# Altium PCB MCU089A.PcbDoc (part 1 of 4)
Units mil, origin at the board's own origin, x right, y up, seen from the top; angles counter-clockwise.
Board outline 2300 x 5500 mil, 4 copper layers (Top Signal, GND, PWR, Bottom Signal), stack 61.6 mil thick; 262 components, 208 nets, 964 pads, 377 vias.
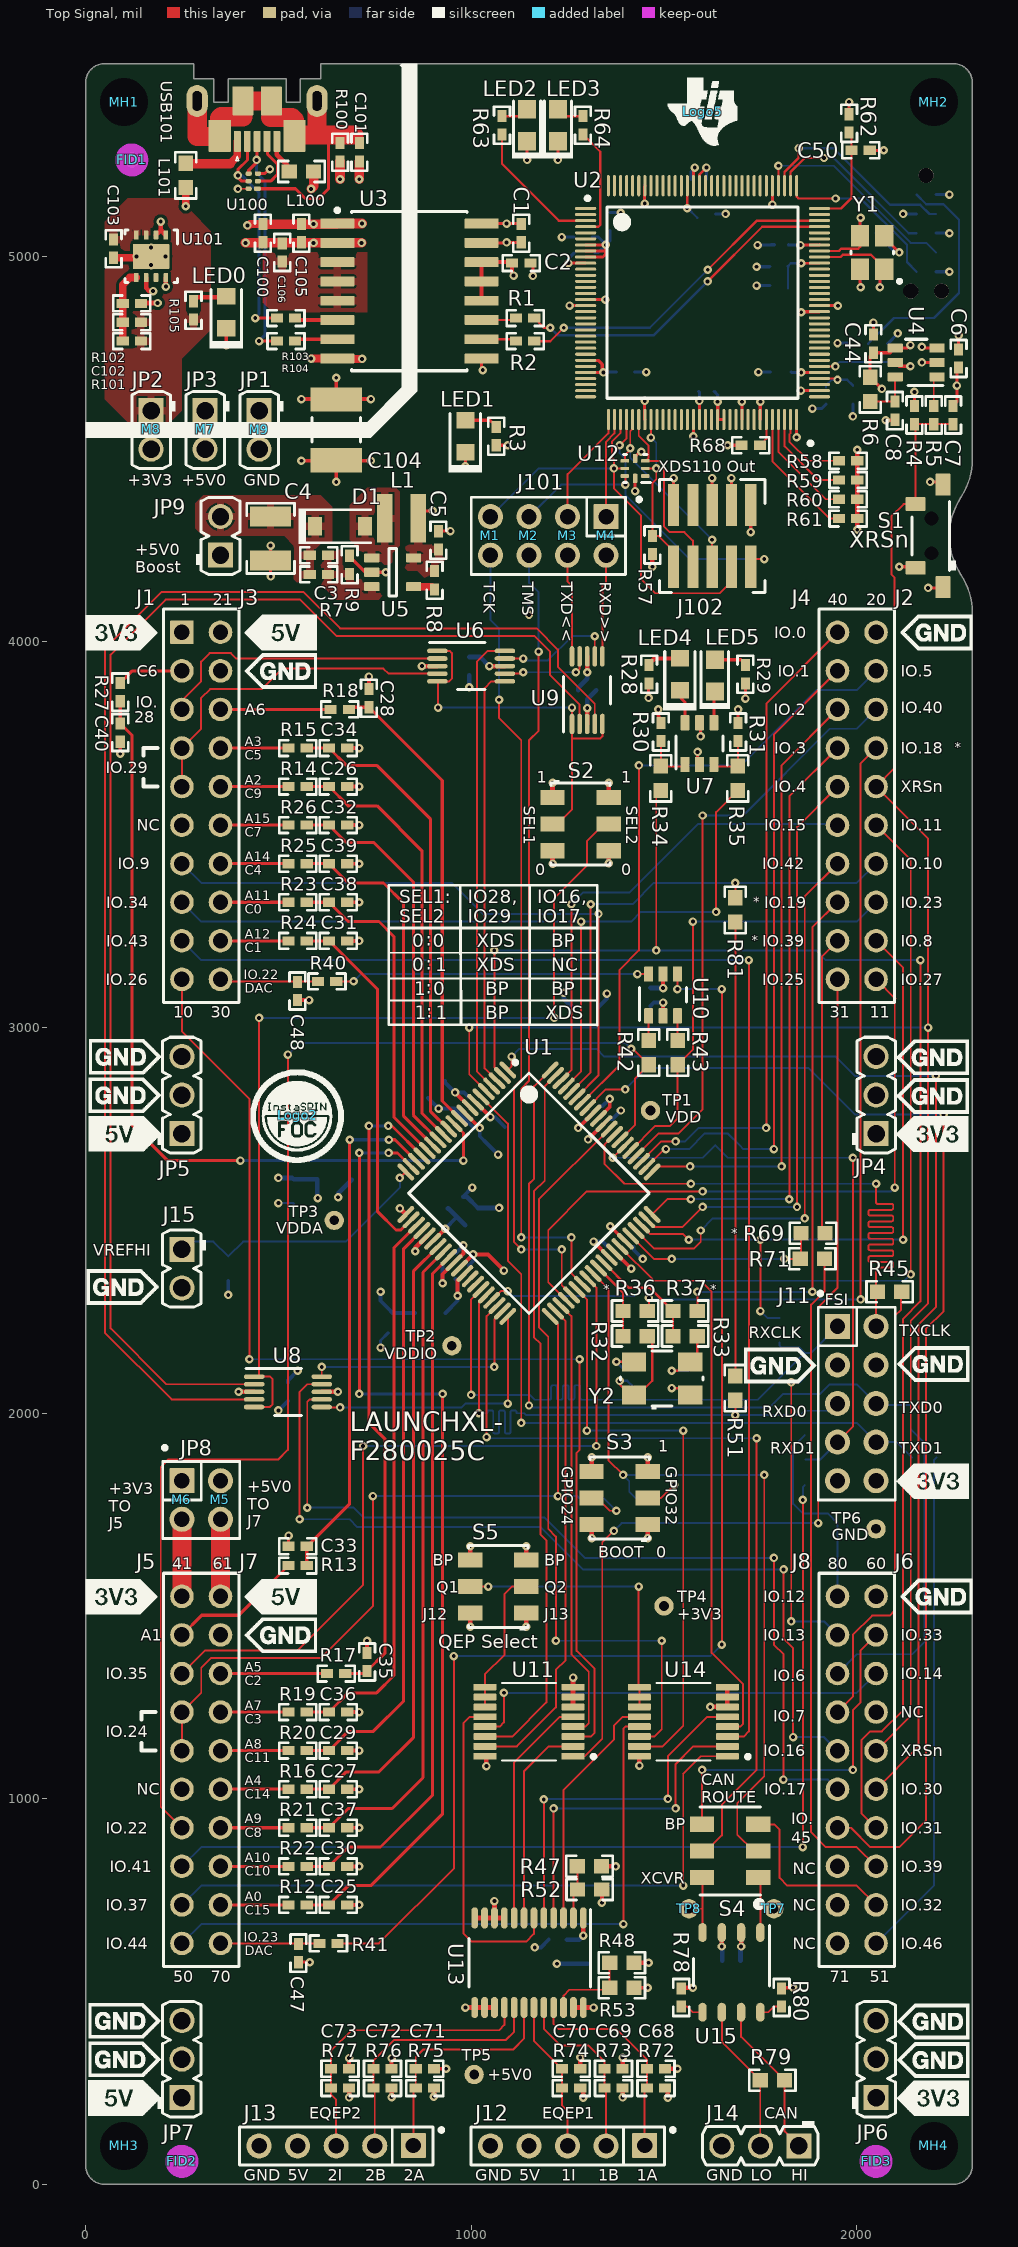
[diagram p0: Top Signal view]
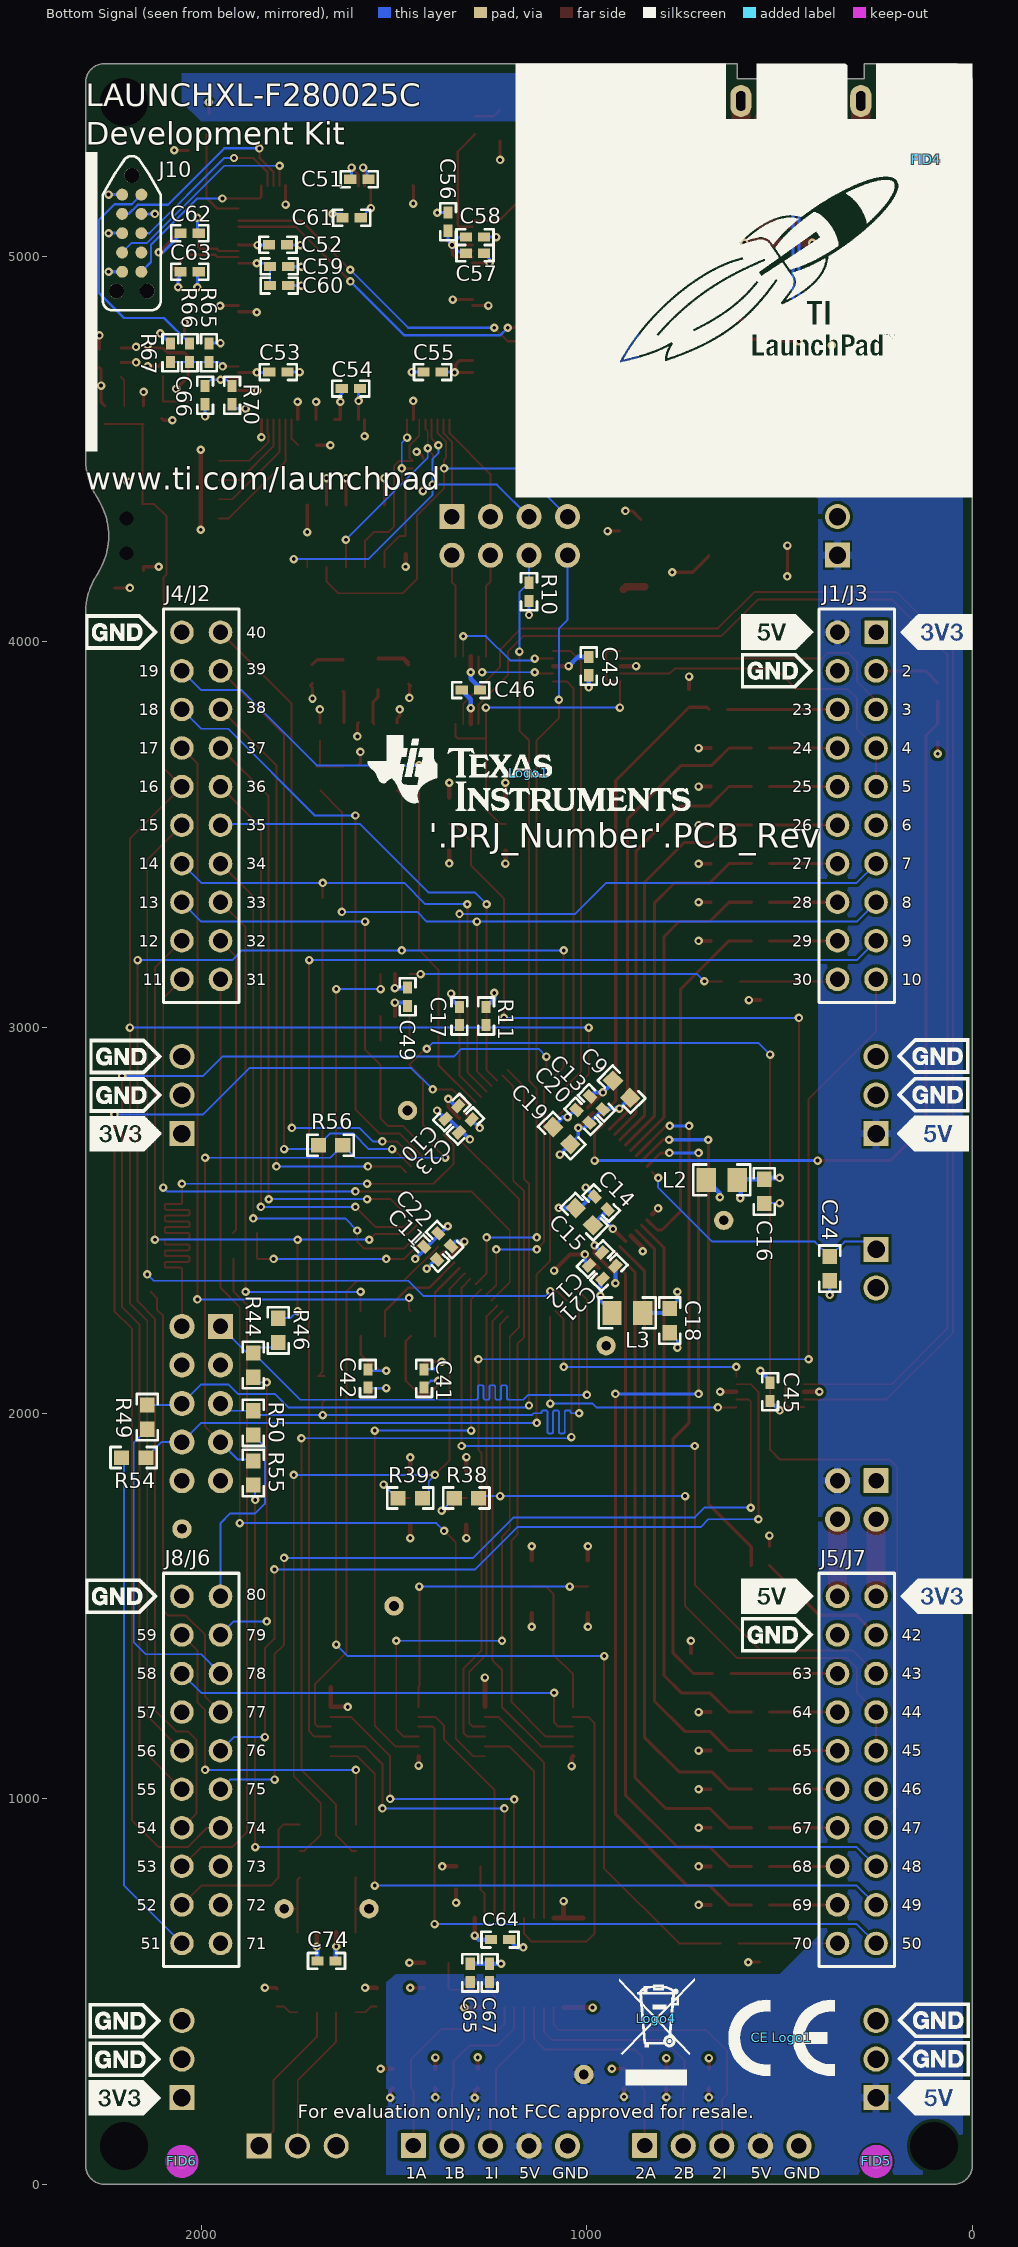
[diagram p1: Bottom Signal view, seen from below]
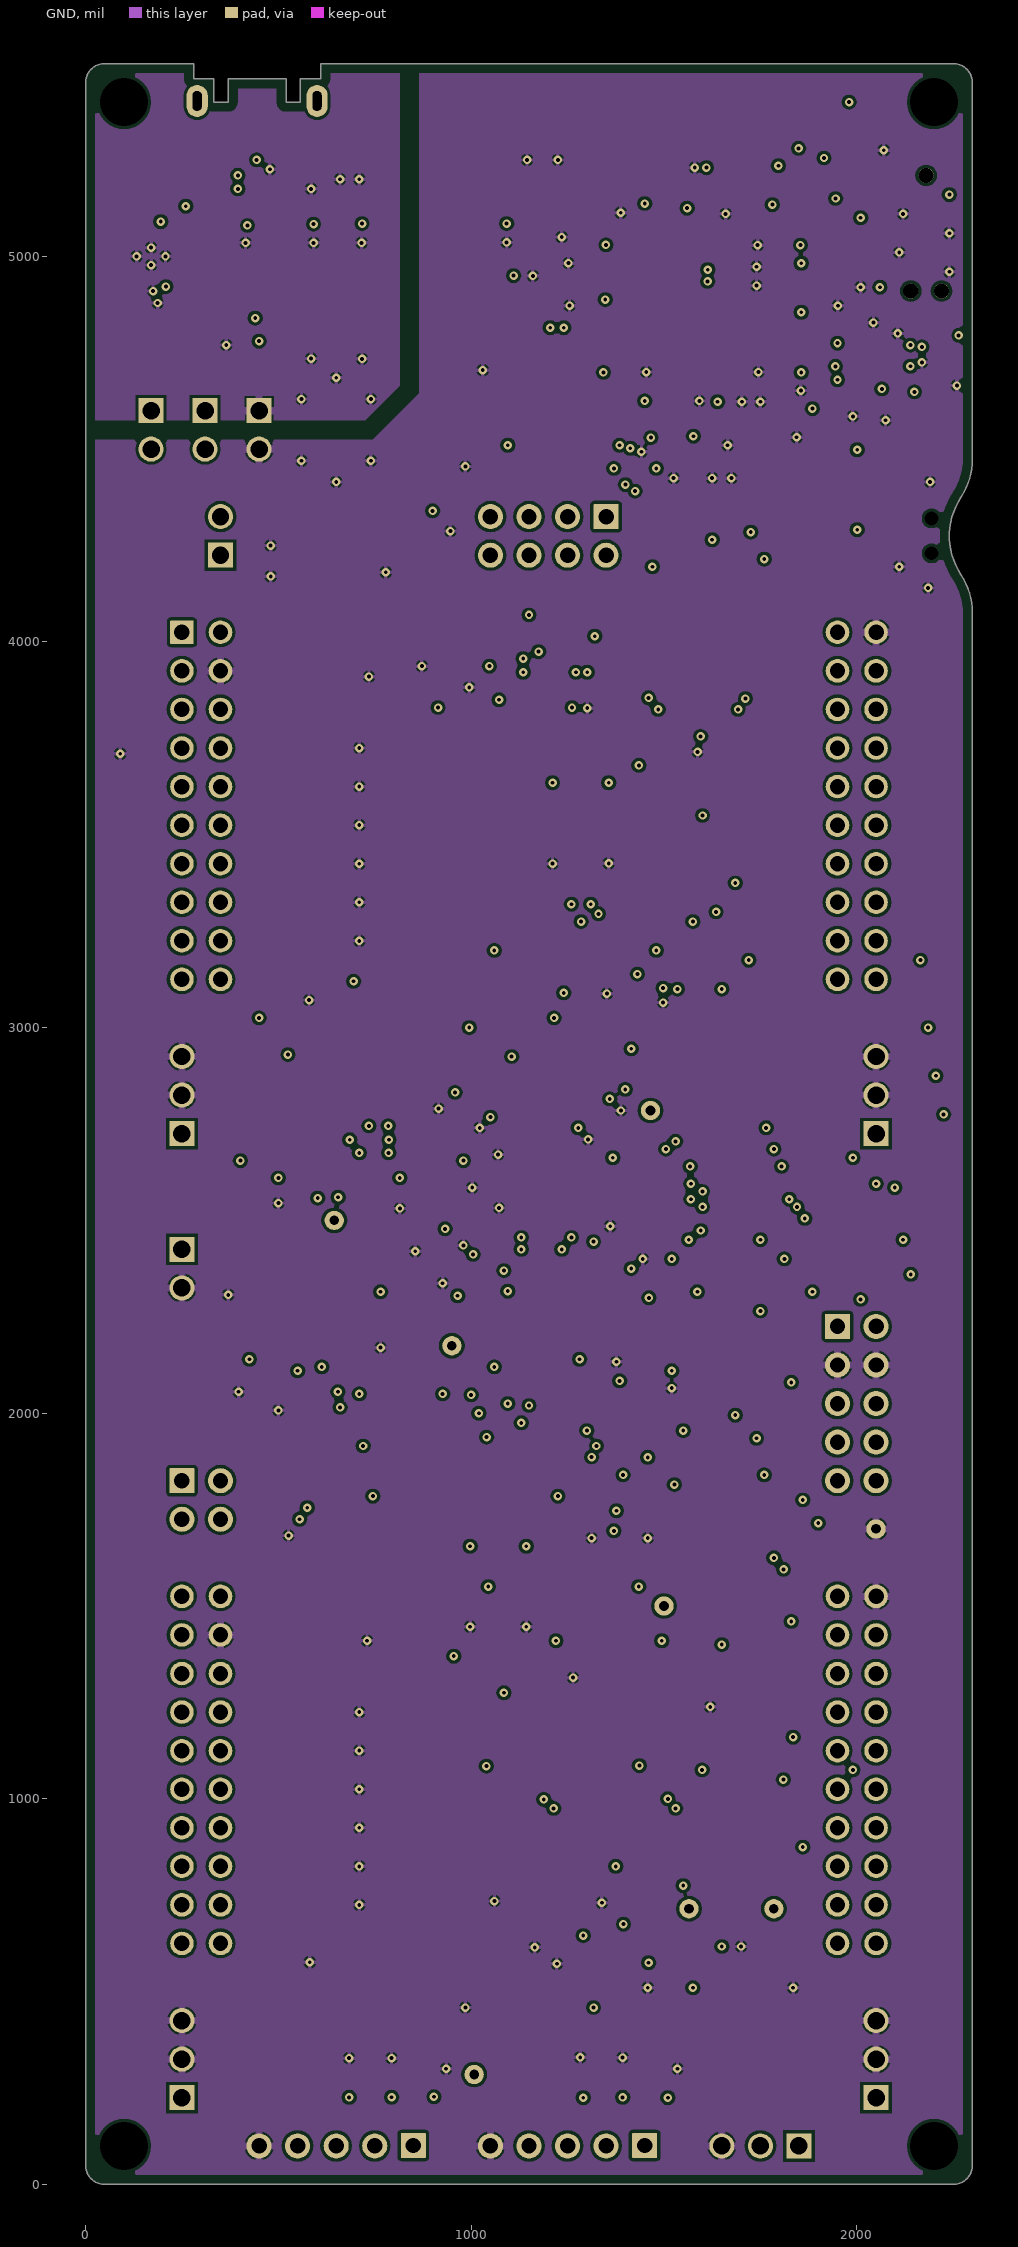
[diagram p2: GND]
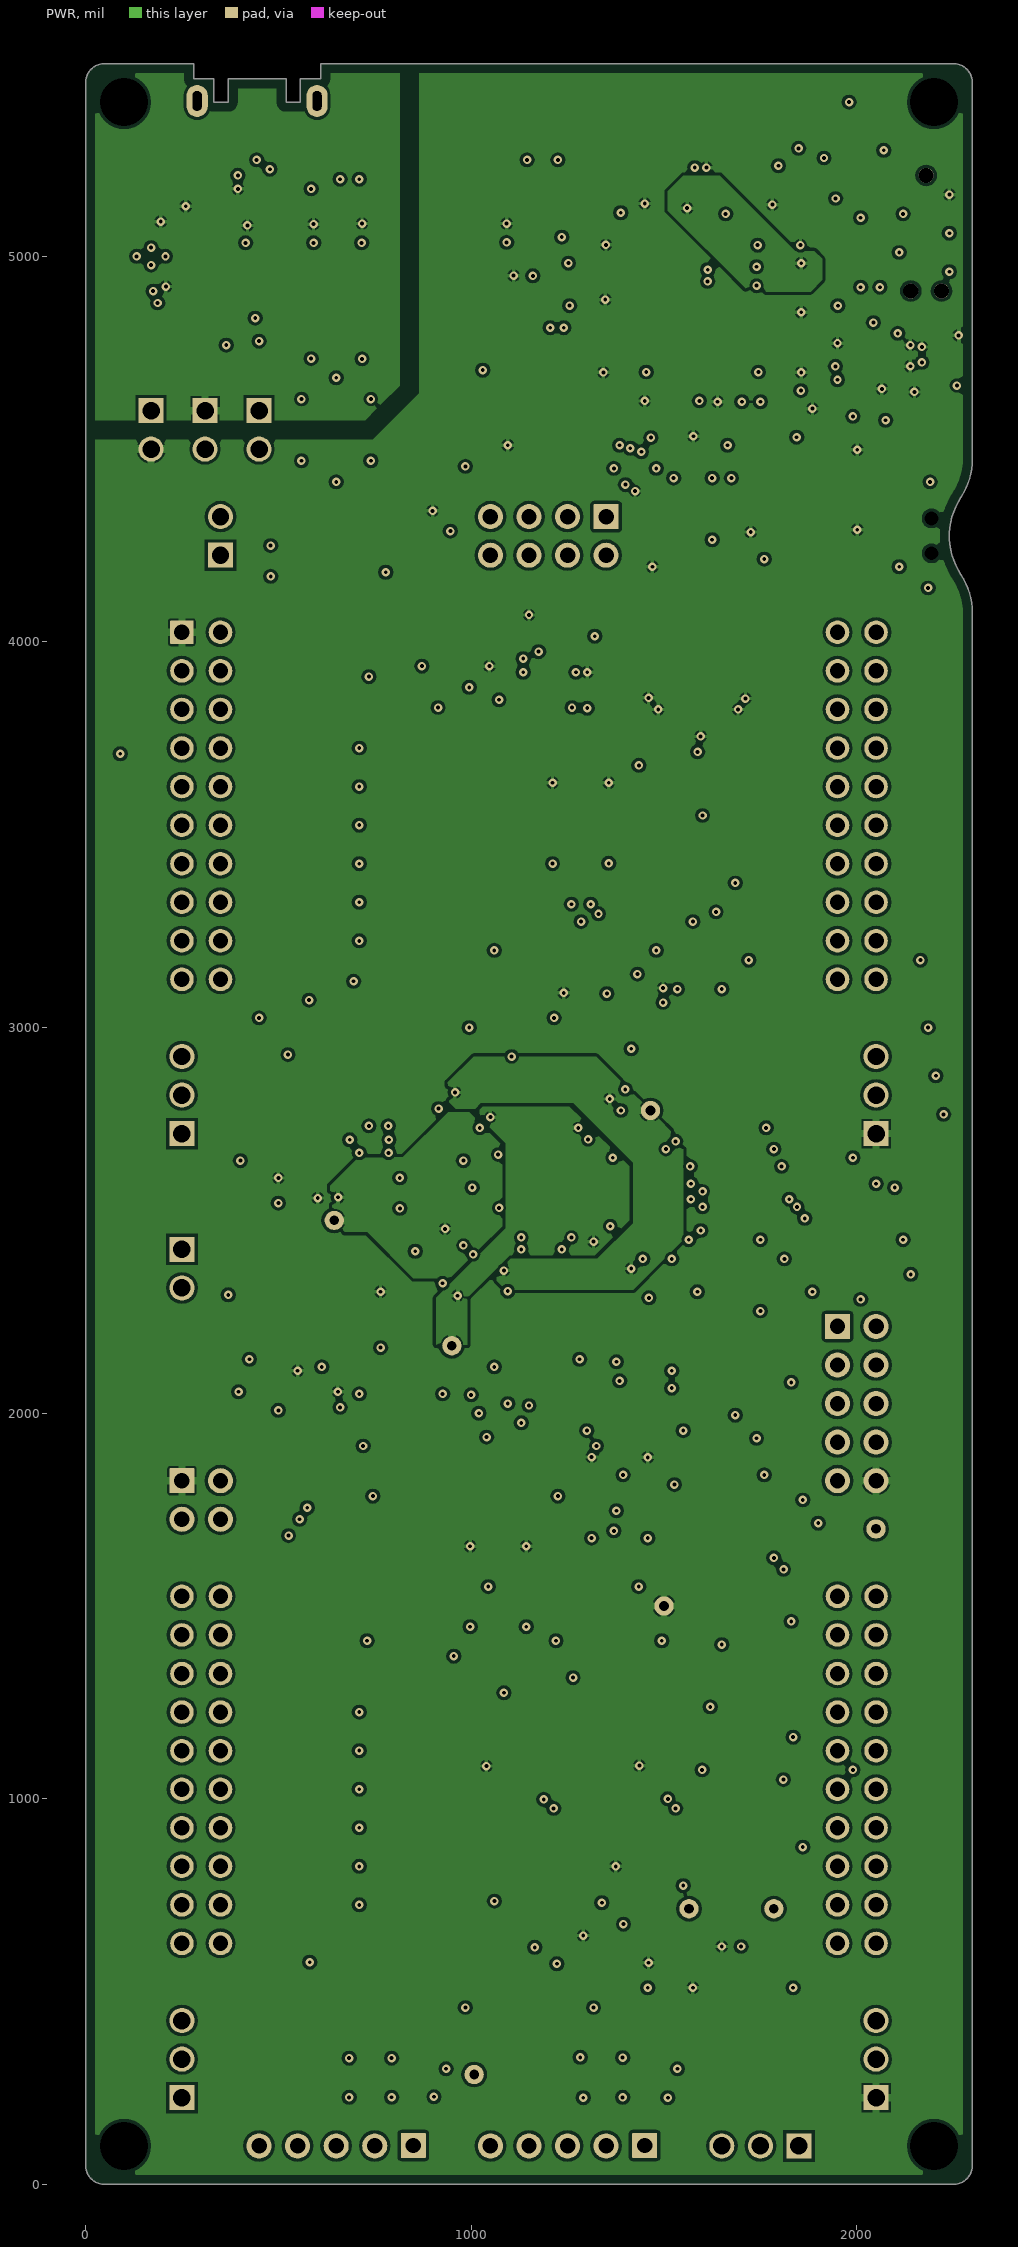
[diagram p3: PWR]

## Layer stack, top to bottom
Top Solder: solder mask 0.4, Solder Resist, Dk 3.5
Top Signal: signal copper 1.4
Dielectric 1: prepreg 8, FR-4, Dk 4.2
GND: signal copper 1.4
Dielectric 2: core 40, FR-4, Dk 4.2
PWR: signal copper 1.4
Dielectric 3: prepreg 8, FR-4, Dk 4.2
Bottom Signal: signal copper 1.4
Bottom Solder: solder mask 0.4, Solder Resist, Dk 3.5

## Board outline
50,0 cw(c50,50) 0,50 0,5450 cw(c50,5450) 50,5500 280,5500 280,5460 333,5460 333,5400 370,5400 370,5460 520,5460 520,5400 557,5400 557,5460 610,5460 610,5500 2250,5500 cw(c2250,5450) 2300,5450 2300,4475 cw(c2118.33,4475) 2270,4375 ccw(c2421.67,4275) 2270,4175 cw(c2118.33,4075) 2300,4075 2300,50 cw(c2250,50) 2250,0

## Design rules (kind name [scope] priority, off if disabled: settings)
AcuteAngle [All] p1: minimum=4.50000000000000E+0001 checktracksonly=TRUE
AssemblyTestPointUsage [All] p1: valid=2
BoardOutlineClearance BoardOutlineClearance_MountingHoles [OnCopper and InComponentClass('Mounting Holes')] p1: gap=40 ignorepadtopadclearanceinfootprint=FALSE
BoardOutlineClearance BoardOutlineClearance_Poly [OnCopper and IsPoly] p2: gap=25 ignorepadtopadclearanceinfootprint=FALSE
BoardOutlineClearance [OnCopper and Not InComponentClass('Logo') and not InComponentClass('FiducialMark') and not InRegion(1000,500,4000,800) and not InPoly] p3: gap=10 ignorepadtopadclearanceinfootprint=FALSE
Clearance Clearance_Boardedge [OnCopper and Not InComponentClass('Logo') and not InComponentClass('FiducialMark') and not IsKeepOut vs IsKeepOut] p1: gap=5 ignorepadtopadclearanceinfootprint=FALSE
Clearance Clearance_FiducialMark [InComponentClass('FiducialMark') vs InComponentClass('FiducialMark')] p2: gap=0 ignorepadtopadclearanceinfootprint=TRUE
Clearance Clearance_Keepouts [((IsTrack Or IsArc) And Not InPoly) And IsFree and IsKeepOut vs ((IsTrack Or IsArc) And Not InPoly) And IsFree and IsKeepOut] p3: gap=5 ignorepadtopadclearanceinfootprint=FALSE
Clearance Clearance_Poly [InPolygon] p4: gap=8 ignorepadtopadclearanceinfootprint=FALSE
Clearance [All] p5: gap=5 ignorepadtopadclearanceinfootprint=FALSE
ComponentClearance "ComponentClearance_overlay to overlay" [OnBottomSilkscreen vs OnTopSilkscreen] p1: gap=0 collisioncheckmode=3 verticalgap=0 showdistances=FALSE
ComponentClearance ComponentClearance_MountingHoles_FiducialMarks [InComponentClass('Mounting Holes') vs InComponentClass('FiducialMark')] p2: gap=50 collisioncheckmode=3 verticalgap=10 showdistances=FALSE
ComponentClearance ComponentClearance_Shunt [InComponentClass('Header') vs InComponentClass('Shunt')] p3: gap=0 collisioncheckmode=3 verticalgap=0 showdistances=FALSE
ComponentClearance ComponentClearance_Logo [InComponentClass('Logo')] p4: gap=0 collisioncheckmode=3 verticalgap=0 showdistances=FALSE
ComponentClearance ComponentClearance_Logo_1 [InComponentClass('Logo') vs InComponentClass('Logo')] p5: gap=0 collisioncheckmode=3 verticalgap=0 showdistances=FALSE
ComponentClearance ComponentClearance_ScrewToNut [(HasFootprint('NY PMS 440 0025 PH')) vs (HasFootprint('Keystone_1902C'))] p6: gap=5 collisioncheckmode=3 verticalgap=10 showdistances=FALSE
ComponentClearance ComponentClearance_MountingHoles [InComponentClass('Mounting Holes')] p7: gap=250 collisioncheckmode=3 verticalgap=100000 showdistances=FALSE
ComponentClearance ComponentClearance_SmallPassives [HasFootprint('0201*') or HasFootprint('0402*') or HasFootprint('0508') or HasFootprint('0603*') or HasFootprint('0612') or HasFootprint('0805*') or HasFootprint('0815*') or HasFootprint('0830*') or HasFootprint('1206*') or HasFootprint('1210*') or HasFootprint('1808*') or HasFootprint('1812*') or HasFootprint('1825*') or HasFootprint('2010*') or HasFootprint('2220*') or HasFootprint('2225*') or HasFootprint('2512*') or HasFootprint('2728*') or HasFootprint('3518*') vs HasFootprint('0201*') or HasFootprint('0402*') or HasFootprint('0508') or HasFootprint('0603*') or HasFootprint('0612') or HasFootprint('0805*') or HasFootprint('0815*') or HasFootprint('0830*') or HasFootprint('1206*') or HasFootprint('1210*') or HasFootprint('1808*') or HasFootprint('1812*') or HasFootprint('1825*') or HasFootprint('2010*') or HasFootprint('2220*') or HasFootprint('2225*') or HasFootprint('2512*') or HasFootprint('2728*') or HasFootprint('3518*')] p8: gap=10 collisioncheckmode=3 verticalgap=0 showdistances=FALSE
ComponentClearance ComponentClearance_THtoSMT [IsThruComponent vs IsSMTComponent] p9: gap=10 collisioncheckmode=3 verticalgap=10 showdistances=FALSE
ComponentClearance ComponentClearance_THtoTH [IsThruComponent vs IsThruComponent] p10: gap=20 collisioncheckmode=3 verticalgap=30 showdistances=FALSE
DiffPairsRouting [All] p1: maxlimit=100 minlimit=10 mostfreqgap=10 toplayer_minwidth=15 toplayer_maxwidth=15 toplayer_prefwidth=15 midlayer1_minwidth=15 midlayer1_maxwidth=15 midlayer1_prefwidth=15 midlayer2_minwidth=15 midlayer2_maxwidth=15 midlayer2_prefwidth=15 bottomlayer_minwidth=15 bottomlayer_maxwidth=15 bottomlayer_prefwidth=15 maxuncoupledlength=1000
FabricationTestPointUsage TestPointUsage [All] p1: valid=2 allowmultiple=FALSE
FabricationTestpoint Testpoint [All] p1: side=3 testpointundercomponent=TRUE minsize=40 maxsize=100 preferedsize=60 minholesize=0 maxholesize=40 preferedholesize=32 testpointgrid=1 allowsidetop=TRUE allowsidebottom=TRUE usegrid=TRUE gridtolerance=0.01
FanoutControl Fanout_LCC [IsLCC] p1: bgadir=Out bgaviamode=Centered fanoutstyle=Auto fanoutdirection=Alternating viagrid=1 // Fanout_LCC (Default Rule)
FanoutControl Fanout_BGA [IsBGA] p2: bgadir=Out bgaviamode=Centered fanoutstyle=Auto fanoutdirection=Alternating viagrid=1 // Fanout_BGA (Default Rule)
FanoutControl Fanout_Default [All] p4: bgadir=Out bgaviamode=Centered fanoutstyle=Auto fanoutdirection=Alternating viagrid=1 // Fanout_Default (Default Rule)
FanoutControl Fanout_Small [(CompPinCount < 5)] p5: bgadir=Out bgaviamode=Centered fanoutstyle=Auto fanoutdirection=OutThenIn viagrid=1 // Fanout_Small (Default Rule)
HoleSize [All] p1: absolutevalues=TRUE maxlimit=251 minlimit=10 maxpercent=80.000 minpercent=20.000
MatchedLengths FSIRX [InNetClass('FSIRX')] p1: tolerance=25 checknetsindiffpair=FALSE checkdiffpairvsdiffpair=TRUE checkxsignals=TRUE checkothers=TRUE
MatchedLengths FSITX [InNetClass('FSITX')] p2: tolerance=25 checknetsindiffpair=FALSE checkdiffpairvsdiffpair=TRUE checkxsignals=TRUE checkothers=TRUE
MinimumAnnularRing MinimumAnnularRing_ThermalPadVias [IsVia and InAnyComponent] p1: minimumring=5
MinimumAnnularRing [All] p2: minimumring=6
MinimumSolderMaskSliver MinimumSolderMaskSliver_Logo [InComponentClass('Logo') vs InComponentClass('Logo')] p1: minsoldermaskwidth=0.7
MinimumSolderMaskSliver [All] p2: minsoldermaskwidth=3
PlaneClearance [All] p1: clearance=5
PlaneConnect [All] p1: planeconnectstyle=Relief reliefexpansion=10 reliefentries=4 reliefconductorwidth=25 reliefairgap=10
PolygonConnect PolygonConnect_via [ViaDiameter = 22] p1: connectstyle=Relief reliefconductorwidth=10 reliefentries=4 polygonreliefangle="90 Angle" airgapwidth=5
PolygonConnect [All] p2: connectstyle=Relief reliefconductorwidth=20 reliefentries=4 polygonreliefangle="90 Angle" airgapwidth=5
RoutingVias ThermalPadVias [IsVia and InAnyComponent] p1: holewidth=7.87 width=19.68 viastyle="Through Hole" minholewidth=7.87 minwidth=19.68 maxholewidth=12.99 maxwidth=23.62
RoutingVias [All] p2: holewidth=10 width=22 viastyle="Through Hole" minholewidth=10 minwidth=22 maxholewidth=40 maxwidth=65
SilkToBoardRegionClearance [Not ((IsComment or IsDesignator) And (Hide <> 'False')) and not InRegion(1000,500,4000,800)] p1:
SilkToSilkClearance SilkToSilkClearance_Pb-FreeLogo [(HasFootprint('Pb-Free_Overlay_Medium') OR HasFootprint('Pb-Free_Overlay_Small')) vs (HasFootprint('Pb-Free_Overlay_Medium') OR HasFootprint('Pb-Free_Overlay_Small'))] p1: silktosilkclearance=0
SilkToSilkClearance [All] p2: silktosilkclearance=3
SilkToSolderMaskClearance SilkToComponentPadClearance [(IsPad or IsFill or IsRegion) and InAnycomponent] p1: minsilkscreentomaskgap=3 clearancetoexposedcopper=TRUE
SilkToSolderMaskClearance "Silk to Solder Mask Opening" [All] p2: minsilkscreentomaskgap=3 clearancetoexposedcopper=TRUE
SolderMaskExpansion [All] p1: expansion=2 istentingtop=FALSE
Width Analog [InNetClass('Analog')] p1: maxlimit=25 minlimit=8 preferedwidth=8
Width [All] p2: maxlimit=100 minlimit=5 preferedwidth=5 checkconnectedcopper=TRUE
14 further rules are at their usual default settings.

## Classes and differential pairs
component class MCU089A_XDS110_USB_Power: C1 C2 C3 C4 C5 C6 C7 C8 C100 C101 C102 C103 C104 C105 C106 D1 JP1 JP2 JP3 JP4 JP5 JP6 JP7 JP9 JP10 L1 L100 L101 LED0 LED1 R1 R2 R3 R4 R5 R6 R7 R8 R9 R100 R101 R102 R103 R104 R105 TP1 TP2 TP3 TP4 TP5 TP6 U3 U4 U5 U100 U101 USB101
component class MCU089A_XDS110_MCU: C50 C51 C52 C53 C54 C55 C56 C57 C58 C59 C60 C61 C62 C63 C66 J10 J101 J102 LED2 LED3 R57 R58 R59 R60 R61 R62 R63 R64 R65 R66 R67 R68 R70 R? U2 U12 Y1
component class MCU089A_F280025C_Device: C9 C10 C11 C12 C13 C14 C15 C16 C17 C18 C19 C20 C21 C22 C23 C24 C25 C26 C27 C28 C29 C30 C31 C32 C33 C34 C35 C36 C37 C38 C39 C40 J15 L2 L3 R10 R11 R12 R13 R14 R15 R16 R17 R18 R19 R20 R21 R22 R23 R24 R25 R26 R27 S1 U1
component class MCU089A_Connectors: C68 C69 C70 C71 C72 C73 C74 J1/J3 J4/J2 J5/J7 J8/J6 J11 J12 J13 J14 JP8 R69 R71 R72 R73 R74 R75 R76 R77 R78 R79 R80 TP7 TP8 U15
component class MCU089A_AltRouting_Misc: C41 C42 C43 C44 C45 C46 C47 C48 C49 C64 C65 C67 LED4 LED5 R28 R29 R30 R31 R32 R33 R34 R35 R36 R37 R38 R39 R40 R41 R42 R43 R44 R45 R46 R47 R48 R49 R50 R51 R52 R53 R54 R55 R56 R81 S2 S3 S4 S5 U6 U7 U8 U9 U10 U11 U13 U14 Y2
component class Header: J11 J12 J13 J14 J15 J101 JP1 JP2 JP3 JP4 JP5 JP6 JP7 JP8 JP9 JP10
component class AssemblyNote: ZZ1 ZZ2 ZZ3
component class FiducialMark: FID1 FID2 FID3 FID4 FID5 FID6
component class MCU089A_Hardware: "CE Logo1" FID1 FID2 FID3 FID4 FID5 FID6 Logo1 Logo2 Logo3 Logo4 Logo5 M1 M2 M3 M4 M5 M6 M7 M8 M9 MH1 MH2 MH3 MH4 ZZ1 ZZ2 ZZ3
component class Logo: Logo1 Logo2 Logo5
net class FSIRX: GPIO12_FSIRXD0 GPIO13_FSIRXCLK GPIO41_FSIRXD1
net class FSITX: GPIO6_FSITXD0 GPIO7_FSITXCLK GPIO46_FSITXD1
component class Shunt: M1 M2 M3 M4 M5 M6 M7 M8 M9

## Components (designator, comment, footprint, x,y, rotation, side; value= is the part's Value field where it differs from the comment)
C1 "GRM155R71A104KA01D" 0402 1130,5060 r90 top value=0.1uF
C2 "GRM155R71A104KA01D" 0402 1130,4982.36 r180 top value=0.1uF
C3 "GRM1555C1E821JA01D" 0402 605,4225 r0 top value=820pF
C4 "885012209028" 1210_220 480,4268.53 r270 top value=10uF
C5 "885012105008" 0402 915,4263.62 r90 top value=4.7uF
C6 "GRM155R71A104KA01D" 0402 2264.02,4735 r90 top value=0.1uF
C7 "GRM155R71E103KA01D" 0402 2249.61,4588.38 r90 top value=0.01uF
C8 "GRM155R71E103KA01D" 0402 2099.02,4600 r270 top value=0.01uF
C9 "GRM188R61A106ME69D" 0603 910,2840 r45 bottom value=10uF
C10 "GRM155R71A104KA01D" 0402 1350,2780 r315 bottom value=0.1uF
C11 "GRM155R71A104KA01D" 0402 1405,2415 r45 bottom value=0.1uF
C12 "GRM155R71A104KA01D" 0402 977.67,2400 r135 bottom value=0.1uF
C13 "GRM155R71A104KA01D" 0402 975,2805 r225 bottom value=0.1uF
C14 "GRM155R71A104KA01D" 0402 962.67,2545 r225 bottom value=0.1uF
C15 "GRM188R61A225KE34D" 0603 1006.58,2510 r45 bottom value=2.2uF
C16 "GRM188R61A225KE34D" 0603 540,2575 r270 bottom value=2.2uF
C17 "GRM155R71A104KA01D" 0402 1330.24,3030 r270 bottom value=0.1uF
C18 "GRM188R61A106ME69D" 0603 785,2240 r270 bottom value=10uF
C19 "GRM188R61A106ME69D" 0603 1065,2720 r225 bottom value=10uF
C20 "GRM155R71A104KA01D" 0402 1010,2770 r45 bottom value=0.1uF
C21 "GRM155R71A104KA01D" 0402 942.67,2365 r315 bottom value=0.1uF
C22 "GRM155R71A104KA01D" 0402 1368.55,2450 r225 bottom value=0.1uF
C23 "GRM155R71A104KA01D" 0402 1315,2745 r135 bottom value=0.1uF
C24 "GRM188R61A225KE34D" 0603 370.07,2375 r270 bottom value=2.2uF
C25 "C1005C0G1H221F050BA" 0402 655,725 r0 top value=220pF
C26 "C1005C0G1H221F050BA" 0402 655,3625 r0 top value=220pF
C27 "C1005C0G1H221F050BA" 0402 655,1025 r0 top value=220pF
C28 "C1005C0G1H221F050BA" 0402 735,3854.31 r90 top value=220pF
C29 "C1005C0G1H221F050BA" 0402 655,1125 r0 top value=220pF
C30 "C1005C0G1H221F050BA" 0402 655,825 r0 top value=220pF
C31 "C1005C0G1H221F050BA" 0402 655,3225 r0 top value=220pF
C32 "C1005C0G1H221F050BA" 0402 655,3525 r0 top value=220pF
C33 "C1005C0G1H221F050BA" 0402 550,1655 r180 top value=220pF
C34 "C1005C0G1H221F050BA" 0402 655,3725 r0 top value=220pF
C35 "C1005C0G1H221F050BA" 0402 730,1355 r90 top value=220pF
C36 "C1005C0G1H221F050BA" 0402 655,1225 r0 top value=220pF
C37 "C1005C0G1H221F050BA" 0402 655,925 r0 top value=220pF
C38 "C1005C0G1H221F050BA" 0402 655,3325 r0 top value=220pF
C39 "C1005C0G1H221F050BA" 0402 655,3425 r0 top value=220pF
C40 "C1005C0G1H221F050BA" 0402 90,3765 r270 top value=220pF
C41 "885012005056" 0402 1422.17,2090 r90 bottom value=15pF
C42 "885012005056" 0402 1567.83,2090 r270 bottom value=15pF
C43 "GRM155R71A104KA01D" 0402 995,3937.39 r270 bottom value=0.1uF
C44 "GRM155R71A104KA01D" 0402 2043.23,4773.62 r270 top value=0.1uF
C45 "GRM155R71A104KA01D" 0402 525,2055.5 r270 bottom value=0.1uF
C46 "GRM155R71A104KA01D" 0402 1300.9,3875 r180 bottom value=0.1uF
C47 "TMK105B7104MV-FR" 0402 551.91,600 r270 top value=0.1uF
C48 "TMK105B7104MV-FR" 0402 549.19,3095 r270 top value=0.1uF
C49 "GRM155R71A104KA01D" 0402 1465,3080 r90 bottom value=0.1uF
C50 "GRM155R71E103KA01D" 0402 2010,5275 r0 top value=0.01uF
C51 "GRM155R71E103KA01D" 0402 1590,5200 r180 bottom value=0.01uF
C52 "GRM155R71E103KA01D" 0402 1801,5030 r180 bottom value=0.01uF
C53 "GRM155R71E103KA01D" 0402 1800,4700 r180 bottom value=0.01uF
C54 "GRM155R70J104KA01D" 0402 1612,4657 r180 bottom value=0.1uF
C55 "GRM155R70J104KA01D" 0402 1400,4700 r0 bottom value=0.1uF
C56 "885012105012" 0402 1360,5090 r90 bottom value=1uF
C57 "885012105012" 0402 1290,5008 r180 bottom value=1uF
C58 "GRM155R71E103KA01D" 0402 1290,5050 r180 bottom value=0.01uF
C59 "GRM155R60J225KE95D" 0402 1798,4974 r180 bottom value=2.2uF
C60 "GRM155R70J104KA01D" 0402 1798,4924 r180 bottom value=0.1uF
C61 "885012105012" 0402 1610,5100 r0 bottom value=1uF
C62 "C0402C120J3GACAUTO" 0402 2030,5060 r0 bottom value=12pF
C63 "C0402C120J3GACAUTO" 0402 2030,4960 r180 bottom value=12pF
C64 "GRM155R71A104KA01D" 0402 1225,635.05 r180 bottom value=0.1uF
C65 "GRM155R71A104KA01D" 0402 1302.4,548.62 r270 bottom value=0.1uF
C66 "GRM155R70J104KA01D" 0402 1990,4640 r270 bottom value=0.1uF
C67 "885012205061" 0402 1252.36,548.62 r90 bottom value=1000pF
C68 "885012205061" 0402 1479.25,300 r0 top value=1000pF
C69 "885012205061" 0402 1369.25,300 r0 top value=1000pF
C70 "885012205061" 0402 1259.25,300 r0 top value=1000pF
C71 "885012205061" 0402 880,300 r0 top value=1000pF
C72 "885012205061" 0402 770,300 r0 top value=1000pF
C73 "885012205061" 0402 660,300 r0 top value=1000pF
C74 "GRM155R71A104KA01D" 0402 1675,580 r180 bottom value=0.1uF
C100 "GRM155R60J225KE95D" 0402 460,5060 r270 top value=2.2uF
C101 "GRM155R71H332KA01D" 0402 710,5270 r270 top value=3300pF
C102 "885012005056" 0402 120,4829 r180 top value=15pF
C103 "GRM155R60J225KE95D" 0402 73,5020 r270 top value=2.2uF
C104 "1812SC103KAT1A" 1812 650,4550 r90 top value=0.01uF
C105 "GRM155R71A104KA01D" 0402 560,5060 r90 top value=0.1uF
C106 "GRM155R71A104KA01D" 0402 510,5010 r270 top value=0.1uF
"CE Logo1" "CE Mark" CE_Mark_5mm 495,380 r180 bottom
D1 "1N5819HW-7-F" SOD-123 660,4300 r0 top value=40V
FID1 "Fiducial" Fiducial10-20 120,5250 r0 top
FID2 "Fiducial" Fiducial10-20 250,60 r0 top
FID3 "Fiducial" Fiducial10-20 2050,60 r0 top
FID4 "Fiducial" Fiducial10-20 120,5250 r180 bottom
FID5 "Fiducial" Fiducial10-20 250,60 r180 bottom
FID6 "Fiducial" Fiducial10-20 2050,60 r180 bottom
J1/J3 "SSQ-110-03-T-D" BoosterPack_40pin_J1J3 300,3575 r180 bottom locked
J4/J2 "SSQ-110-03-T-D" BoosterPack_40pin_J2J4 2000,3575 r180 bottom locked
J5/J7 "SSQ-110-03-T-D" BoosterPack_40pin_J5J7 300,1075 r180 bottom locked
J8/J6 "SSQ-110-03-T-D" BoosterPack_40pin_J6J8 2000,1075 r180 bottom locked
J10 "TC2050-IDC-NL-FP" Tag_TC2050-NL 2180,5060 r180 bottom locked
J11 "TSW-105-07-G-D" TSW-105-07-G-D 2000,2025 r270 top locked
J12 "TSW-105-07-G-S" TSW-105-07-X-S 1250,100 r180 top locked
J13 "TSW-105-07-G-S" TSW-105-07-X-S 650,100 r180 top locked
J14 "61300311121" WURTH_61300311121 1750,100 r180 top locked
J15 "61300211121" WURTH_61300211121 250,2375 r270 top locked
J101 "TSW-104-07-G-D" TSW-104-07-G-D 1200,4275 r180 top
J102 "FTSH-105-01-F-DV-K" Samtec_FTSH-105-01-x-DV-K 1625,4275 r270 top
JP1 "61300211121" WURTH_61300211121 450,4550 r270 top
JP2 "61300211121" WURTH_61300211121 170,4550 r270 top
JP3 "61300211121" WURTH_61300211121 310,4550 r270 top
JP4 "61300311121" WURTH_61300311121 2050,2825 r90 top
JP5 "61300311121" WURTH_61300311121 250,2825 r90 top locked
JP6 "61300311121" WURTH_61300311121 2050,325 r90 top locked
JP7 "61300311121" WURTH_61300311121 250,325 r90 top locked
JP8 "TSW-102-07-G-D" TSW-102-07-G-D 300,1775 r270 top locked
JP9 "61300211121" WURTH_61300211121 350,4275 r90 top
L1 "744025003" WE-TPC_2828 819.47,4320.38 r180 top value=3.3uH
L2 "742792063" 0805_HV 650,2605 r180 bottom value="60 ohm"
L3 "742792022" 0805_HV 895,2260 r0 bottom value="220 ohm"
L100 "742792620" 0603 560,5220 r0 top value="100 ohm"
L101 "742792620" 0603 260,5210 r270 top value="100 ohm"
LED0 "150080SS75000" WL-SMCW_RED_0805 365,4855 r90 top value=Red
LED1 "150080SS75000" WL-SMCW_RED_0805 985,4533.66 r90 top value=Red
LED2 "LTST-C170TBKT" LTST-C170TBKT_Blue 1145,5340 r270 top value=Blue
LED3 "LTST-C170TBKT" LTST-C170TBKT_Blue 1225,5340 r270 top value=Blue
LED4 "150080SS75000" WL-SMCW_RED_0805 1541.41,3916.37 r90 top value=Red
LED5 "LTST-C171GKT" LED_LTST-C171 1632.04,3912.53 r270 top value=Green
Logo1 "Texas Instruments" TI_Stacked_Overlay_Small 1150,3660 r180 bottom
Logo2 "INSTASPIN_FOC_LOGO" INSTASPIN_FOC_LOGO 550,2773.1 r0 top
Logo3 "FCC disclaimer" FCC_disclaimer 3295,160 r180 bottom
Logo4 "WEEE logo" WEEE_Minimum 820,430 r180 bottom
Logo5 "Texas Instruments" TI_Symbol_Overlay_Small 1600,5375 r0 top
M1 "60900213421" Wurth_60900213421 1050,4275 r270 top
M2 "60900213421" Wurth_60900213421 1150,4275 r90 top
M3 "60900213421" Wurth_60900213421 1250,4275 r90 top
M4 "60900213421" Wurth_60900213421 1350,4275 r90 top
M5 "60900213421" Wurth_60900213421 350,1775 r90 top
M6 "60900213421" Wurth_60900213421 250,1775 r90 top
M7 "60900213421" Wurth_60900213421 310,4551 r90 top
M8 "60900213421" Wurth_60900213421 170,4551 r90 top
M9 "60900213421" Wurth_60900213421 450,4550 r90 top
MH1 "MTG_NoPads" NPTH125mil 100,5400 r0 top
MH2 "MTG_NoPads" NPTH125mil 2200,5400 r0 top
MH3 "MTG_NoPads" NPTH125mil 100,100 r0 top
MH4 "MTG_NoPads" NPTH125mil 2200,100 r0 top
R1 "CRCW040224R3FKED" 0402 1140,4840 r0 top value=24.3
R2 "CRCW040224R3FKED" 0402 1140,4780 r0 top value=24.3
R3 "CRCW0402680RJNED" 0402 1065,4533.66 r270 top value=680
R4 "CRCW04022K20JNED" 0402 2149.61,4588.38 r90 top value=2.2k
R5 "CRCW04020000Z0ED" 0402 2199.61,4588.38 r270 top value=0
R6 "CRCW06032K20JNEA" 0603 2034.61,4655.12 r90 top value=2.2k
R7 "RC0402FR-0730K1L" 0402 605,4175 r180 top value=30.1k
R8 "CRCW040210K0JNED" 0402 905,4160 r90 top value=10k
R9 "CRCW040210K0JNED" 0402 685,4200 r270 top value=10k
R10 "CRCW04022K20JNED" 0402 1150,4130 r270 bottom value=2.2k
R11 "CRCW04022K20JNED" 0402 1261.06,3030 r90 bottom value=2.2k
R12 "ERJ-2GE0R00X" 0402 550,725 r0 top value=0
R13 "ERJ-2GE0R00X" 0402 550,1605 r0 top value=0
R14 "ERJ-2GE0R00X" 0402 550,3625 r0 top value=0
R15 "ERJ-2GE0R00X" 0402 550,3725 r0 top value=0
R16 "ERJ-2GE0R00X" 0402 550,1025 r0 top value=0
R17 "ERJ-2GE0R00X" 0402 650,1325 r0 top value=0
R18 "ERJ-2GE0R00X" 0402 659.31,3825 r0 top value=0
R19 "ERJ-2GE0R00X" 0402 550,1225 r0 top value=0
R20 "ERJ-2GE0R00X" 0402 550,1125 r0 top value=0
R21 "ERJ-2GE0R00X" 0402 550,925 r0 top value=0
R22 "ERJ-2GE0R00X" 0402 550,825 r0 top value=0
R23 "ERJ-2GE0R00X" 0402 550,3325 r0 top value=0
R24 "ERJ-2GE0R00X" 0402 550,3225 r0 top value=0
R25 "ERJ-2GE0R00X" 0402 550,3425 r0 top value=0
R26 "ERJ-2GE0R00X" 0402 550,3525 r0 top value=0
R27 "ERJ-2GE0R00X" 0402 90,3870 r270 top value=0
R28 "CRCW0402680RJNED" 0402 1461.41,3916.37 r270 top value=680
R29 "CRCW0402680RJNED" 0402 1711.41,3916.37 r270 top value=680
R30 "CRCW040210M0JNED" 0402 1492.04,3766.53 r90 top value=10Meg
R31 "CRCW040210M0JNED" 0402 1692.04,3766.53 r90 top value=10Meg
R32 "CRCW06030000Z0EA" 0603 1425.36,2200 r0 top value=0
R33 "CRCW06030000Z0EA" 0603 1555,2200 r0 top value=0
R34 "CRCW06030000Z0EA" 0603 1492.04,3646.53 r90 top value=0
R35 "CRCW06030000Z0EA" 0603 1691.04,3646.53 r90 top value=0
R36 "CRCW06030000Z0EA" 0603 1425.36,2265 r180 top value=0
R37 "CRCW06030000Z0EA" 0603 1555,2265 r180 top value=0
R38 "RC0603FR-0710KL" 0603 1312.28,1780 r0 bottom value=10.0k
R39 "RC0603FR-0710KL" 0603 1457.95,1780 r180 bottom value=10.0k
R40 "CRCW04021K00FKED" 0402 626.38,3120 r180 top value=1.00k
R41 "CRCW04021K00FKED" 0402 630,625 r180 top value=1.00k
R42 "CRCW06030000Z0EA" 0603 1460.2,2935 r90 top value=0
R43 "CRCW06030000Z0EA" 0603 1535.63,2935 r90 top value=0
R44 "CRCW06030000Z0EA" 0603 1865,2125 r270 bottom value=0
R45 "CRCW06030000Z0EA" 0603 2085,2314.88 r0 top value=0
R46 "CRCW06030000Z0EA" 0603 1800,2215 r90 bottom value=0
R47 "CRCW06030000Z0EA" 0603 1306.85,825 r0 top value=0
R48 "CRCW06032K20JNEA" 0603 1390.75,575 r0 top value=2.2k
R49 "CRCW06030000Z0EA" 0603 2140,1990 r270 bottom value=0
R50 "CRCW06030000Z0EA" 0603 1865,1975 r270 bottom value=0
R51 "CRCW06030000Z0EA" 0603 1685,2065 r90 top value=0
R52 "CRCW06030000Z0EA" 0603 1307.4,765 r180 top value=0
R53 "CRCW06030000Z0EA" 0603 1390.75,510 r0 top value=0
R54 "CRCW06030000Z0EA" 0603 2175,1885 r0 bottom value=0
R55 "CRCW06030000Z0EA" 0603 1865,1845 r270 bottom value=0
R56 "CRCW06030000Z0EA" 0603 1664.56,2695 r0 bottom value=0
R57 "CRCW04023K30JNED" 0402 1470,4251.31 r270 top value=3.3k
R58 "CRCW04021K00FKED" 0402 1977.48,4470 r0 top value=1.00k
R59 "CRCW04021K00FKED" 0402 1977.48,4420 r0 top value=1.00k
R60 "CRCW04021K00FKED" 0402 1977.48,4370 r0 top value=1.00k
R61 "CRCW04021K00FKED" 0402 1977.48,4320 r0 top value=1.00k
R62 "CRCW0402100RJNED" 0402 1980,5345 r270 top value=100
R63 "ERJ-2RKF4700X" 0402 1080,5340 r270 top value=470
R64 "ERJ-2RKF4700X" 0402 1290,5340 r270 top value=470
R65 "CRCW040210K0JNED" 0402 1980,4750 r90 bottom value=10k
R66 "CRCW0402100RJNED" 0402 2030,4750 r270 bottom value=100
R67 "CRCW040210K0JNED" 0402 2080,4750 r270 bottom value=10k
R68 "CRCW04024K87FKED" 0402 1725,4510.11 r0 top value=4.87k
R69 "CRCW06030000Z0EA" 0603 1886.5,2466.8 r0 top value=0
R70 "CRCW040251R0JNED" 0402 1920,4640 r270 bottom value=51
R71 "CRCW06030000Z0EA" 0603 1885,2400.47 r180 top value=0
R72 "CRCW04021K00FKED" 0402 1479.25,250 r0 top value=1.00k
R73 "CRCW04021K00FKED" 0402 1369.25,250 r0 top value=1.00k
R74 "CRCW04021K00FKED" 0402 1259.25,250 r0 top value=1.00k
R75 "CRCW04021K00FKED" 0402 880,250 r0 top value=1.00k
R76 "CRCW04021K00FKED" 0402 770,250 r0 top value=1.00k
R77 "CRCW04021K00FKED" 0402 660,250 r0 top value=1.00k
R78 "CRCW040210K0JNED" 0402 1544.88,485 r90 top value=10k
R79 "RC0603FR-07120RL" 0603 1781.1,270 r0 top value=120
R80 "CRCW040210K0JNED" 0402 1805,485 r270 top value=10k
R81 "CRCW06030000Z0EA" 0603 1685,3305 r90 top value=0
R100 "CRCW04021M00FKED" 0402 660,5270 r90 top value=1.00Meg
R101 "CRCW040251K0FKED" 0402 120,4780 r0 top
R102 "CRCW040230K0FKED" 0402 120,4878 r180 top value=30.0k
R103 "CRCW040224R3FKED" 0402 520,4840 r0 top value=24.3
R104 "CRCW040224R3FKED" 0402 520,4780 r0 top value=24.3
R105 "CRCW0402680RJNED" 0402 280,4860 r270 top value=680
S1 "1188E-1K2-V-TR" SW_1188E 2180,4275 r180 top
S2 "CAS-D20TA" SW_CAS-D20TA 1283.81,3527.63 r0 top
S3 "CAS-D20TA" SW_CAS-D20TA 1385.12,1780 r180 top
S4 "CAS-220TA" SW_CAS-220TA 1671.73,865 r180 top
S5 "CAS-D20TA" SW_CAS-D20TA 1070.18,1550.5 r180 top
TP1 "TESTPOINT" TP_50MIL-25MILHOLE 1465,2785 r0 top
TP2 "TESTPOINT" TP_50MIL-25MILHOLE 950,2175 r0 top
TP3 "TESTPOINT" TP_50MIL-25MILHOLE 645,2500 r0 top
TP4 "TESTPOINT" TP_50MIL-25MILHOLE 1500,1500 r0 top
TP5 "TESTPOINT" TP_50MIL-25MILHOLE 1007.8,285 r0 top
TP6 "TESTPOINT" TP_50MIL-25MILHOLE 2050,1700 r0 top
TP7 "TESTPOINT" TP_50MIL-25MILHOLE 1785,715 r90 top
TP8 "TESTPOINT" TP_50MIL-25MILHOLE 1565,715 r90 top
U1 "TMS320F280025CPNSR" PN0080A-MFG 1149.98,2570.55 r315 top
U2 "MSP432E401YTPDT" PDT0128A 1600,4880 r0 top locked
U3 "ADuM3160BRWZ" SOIC-16 840,4910 r0 top
U4 "TPS3702CX33DDCR" DDC0006A_N 2154.02,4725 r180 top
U5 "LMR62421XMFX/NOPB" DBV0005A_N 796.47,4180.77 r0 top
U6 "TS5A23157DGSR" DGS0010A_N 999.97,3937.39 r0 top
U7 "SN74LVC2G07DBVR" DBV0006A_N 1592.04,3736.53 r90 top
U8 "TS5A23157DGSR" DGS0010A_N 525,2055.5 r0 top
U9 "TS5A23157DGSR" DGS0010A_N 1300.9,3875 r90 top
U10 "SN74LVC2G34DBVR" DBV0006A_N 1497.6,3084.62 r90 top
U11 "SN74LV4053APWR" PW0016A-MFG 1150,1200 r180 top
U12 "TPD6E004RSER" RSE0008A 1425,4450 r180 top
U13 "SN74LVC8T245PW" PW0024A_N 1150,575 r270 top
U14 "SN74LV4053APWR" PW0016A-MFG 1550.38,1200 r180 top
U15 "SN65HVD234DR" D0008A_L 1675,550 r270 top
U100 "TPD4E004DRYR" DRY0006A 435,5195 r180 top
U101 "TPS79601DRBR" DRB0008B 170,5000 r270 top
USB101 "1051640001" Molex_1051640001 445,5460 r180 top
Y1 "NX3225GA-16.000M-STD-CRG-1" NDK_NX3225GA 2040,5010 r180 top
Y2 "ECS-200-18-30B-AGN-TR" ECS_ECX-53B 1495,2090 r90 top
ZZ1 "These assemblies are ESD sensitive, ESD precautions shall be observed." AssemblyNote 250,7290 r0 top
ZZ2 "These assemblies must be clean and free from flux and all contaminants. Use of no clean flux is not acceptable." AssemblyNote 250,7165 r0 top
ZZ3 "These assemblies must comply with workmanship standards IPC-A-610 Class 2, unless otherwise specified." AssemblyNote 250,7040 r0 top

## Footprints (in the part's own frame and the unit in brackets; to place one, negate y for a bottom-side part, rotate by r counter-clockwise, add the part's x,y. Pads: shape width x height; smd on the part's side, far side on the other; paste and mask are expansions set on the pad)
0402 [mm] "0402 from SM-752 data"
  rect 0.8x0.6 smd: 1(-0.6,0) 2(0.6,0)
  silkscreen extent -1.22,-0.52 1.22,0.52, body extent -0.55,-0.3 0.55,0.3, height 0.6
0603 [mm] "0603 from SM-752 data"
  rect 1x0.95 smd: 1(-0.8,0) 2(0.8,0)
  silkscreen extent -1.52,-0.69 1.52,0.69, body extent -0.87,-0.47 0.87,0.47, height 1
0805_HV [mil] "0805 with 30mil clearance between pads"
  rect 50x63 smd: 1(-40,0) 2(40,0)
  silkscreen extent -74,-40 74,40, body extent -43,-29 43,29, height 57
1210_220 [mm] "1210"
  rect 1.3x2.7 smd: 1(-1.45,0) 2(1.45,0)
  silkscreen extent -2.32,-1.57 2.32,1.57, body extent -1.7,-1.35 1.7,1.35, height 2.2
1812 [mm]
  rect 1.6x3.4 smd: 1(-2,0) 2(2,0)
  silkscreen extent -0.8,-1.6 0.8,1.6, body extent -2.4,-1.7 2.4,1.7, height 1.35
AssemblyNote [mil] "Assembly Note"
BoosterPack_40pin_J1J3 [mm] "Receptacle, 2.54mm, 10x2, TH"
  rrect6% 1.55x1.55 hole 1.02: 1(1.27,11.43)
  round 1.55 hole 1.02: 2(1.27,8.89) 3(1.27,6.35) 4(1.27,3.81) 5(1.27,1.27) 6(1.27,-1.27) 7(1.27,-3.81) 8(1.27,-6.35) 9(1.27,-8.89) 10(1.27,-11.43) 21(-1.27,11.43) 22(-1.27,8.89) 23(-1.27,6.35) 24(-1.27,3.81) 25(-1.27,1.27) 26(-1.27,-1.27) 27(-1.27,-3.81) 28(-1.27,-6.35) 29(-1.27,-8.89) 30(-1.27,-11.43)
  silkscreen extent -7.62,-12.95 7.62,12.95, body extent -2.48,-12.95 2.48,12.95, height 8.51
BoosterPack_40pin_J2J4 [mm] "Receptacle, 2.54mm, 10x2, TH"
  round 1.55 hole 1.02: 11(-1.27,-11.43) 12(-1.27,-8.89) 13(-1.27,-6.35) 14(-1.27,-3.81) 15(-1.27,-1.27) 16(-1.27,1.27) 17(-1.27,3.81) 18(-1.27,6.35) 19(-1.27,8.89) 20(-1.27,11.43) 31(1.27,-11.43) 32(1.27,-8.89) 33(1.27,-6.35) 34(1.27,-3.81) 35(1.27,-1.27) 36(1.27,1.27) 37(1.27,3.81) 38(1.27,6.35) 39(1.27,8.89) 40(1.27,11.43)
  silkscreen extent -7.62,-12.95 2.48,12.95, body extent -2.48,-12.95 2.48,12.95, height 8.51
BoosterPack_40pin_J5J7 [mm] "Receptacle, 2.54mm, 10x2, TH"
  round 1.55 hole 1.02: 41(1.27,11.43) 42(1.27,8.89) 43(1.27,6.35) 44(1.27,3.81) 45(1.27,1.27) 46(1.27,-1.27) 47(1.27,-3.81) 48(1.27,-6.35) 49(1.27,-8.89) 50(1.27,-11.43) 61(-1.27,11.43) 62(-1.27,8.89) 63(-1.27,6.35) 64(-1.27,3.81) 65(-1.27,1.27) 66(-1.27,-1.27) 67(-1.27,-3.81) 68(-1.27,-6.35) 69(-1.27,-8.89) 70(-1.27,-11.43)
  silkscreen extent -7.62,-12.95 7.62,12.95, body extent -2.48,-12.95 2.48,12.95, height 8.51
BoosterPack_40pin_J6J8 [mm] "Receptacle, 2.54mm, 10x2, TH"
  round 1.55 hole 1.02: 51(-1.27,-11.43) 52(-1.27,-8.89) 53(-1.27,-6.35) 54(-1.27,-3.81) 55(-1.27,-1.27) 56(-1.27,1.27) 57(-1.27,3.81) 58(-1.27,6.35) 59(-1.27,8.89) 60(-1.27,11.43) 71(1.27,-11.43) 72(1.27,-8.89) 73(1.27,-6.35) 74(1.27,-3.81) 75(1.27,-1.27) 76(1.27,1.27) 77(1.27,3.81) 78(1.27,6.35) 79(1.27,8.89) 80(1.27,11.43)
  silkscreen extent -7.62,-12.95 2.48,12.95, body extent -2.48,-12.95 2.48,12.95, height 8.51
CE_Mark_5mm [mil] "Minimum text height for CE Mark"
  silkscreen extent -138,-98 138,98
D0008A_L [mm] "SOIC, 8-Leads, Body 4.9x3.9mm, Pitch 1.27mm, IPC High Density"
  oval 1.25x0.55 smd: 1(-2.625,1.905) 2(-2.625,0.635) 3(-2.625,-0.635) 4(-2.625,-1.905) 5(2.625,-1.905) 6(2.625,-0.635) 7(2.625,0.635) 8(2.625,1.905)
  silkscreen extent -3.1,-2.5 0.9,2.5, body extent -3,-2.45 3,2.45, height 1.63
DBV0005A_N [mm] "SOT23, 5-Leads, Body 2.9x1.6mm, Pitch 0.95mm, Lead Span 2.8mm, IPC Medium Density"
  rrect17% 1x0.6 smd: 1(-1.375,0.95) 2(-1.375,0) 3(-1.375,-0.95) 4(1.375,-0.95) 5(1.375,0.95)
  silkscreen extent -0.25,-1.55 0.25,1.55, body extent -1.42,-1.46 1.42,1.46, height 1.09
DBV0006A_N [mm] "SOT23, 6-Leads, Body 2.9x1.6mm, Pitch 0.95mm, Lead Span 2.8mm, IPC Medium Density"
  rrect17% 1x0.6 smd: 1(-1.375,0.95) 2(-1.375,0) 3(-1.375,-0.95) 4(1.375,-0.95) 5(1.375,0) 6(1.375,0.95)
  silkscreen extent -1.67,-1.55 0.5,1.55, body extent -1.42,-1.46 1.42,1.46, height 1.12
DDC0006A_N [mm]
  rrect17% 1x0.6 smd: 1(-1.375,0.95) 2(-1.375,0) 3(-1.375,-0.95) 4(1.375,-0.95) 5(1.375,0) 6(1.375,0.95)
  silkscreen extent -1.75,-1.52 0.7,1.53, body extent -1.43,-1.48 1.43,1.49, height 0.92
DGS0010A_N [mm] "TSSOP, 10-Leads, Body 3x3mm, Pitch 0.5mm, IPC Medium Density"
  oval 1.35x0.3 smd: 1(-2.225,1) 2(-2.225,0.5) 3(-2.225,0) 4(-2.225,-0.5) 5(-2.225,-1) 6(2.225,-1) 7(2.225,-0.5) 8(2.225,0) 9(2.225,0.5) 10(2.225,1)
  silkscreen extent -2.75,-1.55 0.9,1.55, body extent -2.45,-1.5 2.45,1.5, height 0.96
DRB0008B [mm] "SON, 8-Leads, Body 3x3mm, Pitch 0.65mm, Thermal Pad 2.4x1.65mm, TI Recommended"
  rrect33% 0.6x0.3 smd: 1(-1.4,0.975) 2(-1.4,0.325) 3(-1.4,-0.325) 4(-1.4,-0.975) 5(1.4,-0.975) 6(1.4,-0.325) 7(1.4,0.325) 8(1.4,0.975)
  rrect9% 1.47x1.06 on Top Paste: 9(0,0.63) 9(0,-0.63)
  rrect6% 1.65x2.4 smd paste-1.2: 9(0,0)
  silkscreen extent -1.73,-1.73 1.73,1.73, body extent -1.5,-1.5 1.5,1.5, height 0.96
DRY0006A [mm] "USON-6"
  rrect67% 0.45x0.3 smd paste-0.05 mask-0.05: 1(-0.275,0.5)
  rrect67% 0.4x0.3 smd paste-0.05 mask-0.05: 2(-0.3,0) 3(-0.3,-0.5) 4(0.3,-0.5) 5(0.3,0) 6(0.3,0.5)
  body extent -0.5,-0.72 0.5,0.73, height 0.58
ECS_ECX-53B [mm] "SMD, 4-Leads, Body 5x3.2mm"
  rect 1.25x1.6 smd: 1(-1.1,1.85) 2(-1.1,-1.85) 3(1.1,-1.85) 4(1.1,1.85)
  silkscreen extent -2.05,-2.7 1.83,2.73, body extent -1.7,-2.6 1.7,2.6, height 0.86
FCC_disclaimer [mil]
Fiducial10-20 [mm]
  round 1 smd mask+0.5: 1(0,0)
  Top Signal keep-out circle w1.178: c0,0 r0.5
INSTASPIN_FOC_LOGO [mil] "INSTASPIN FOC LOGO"
  silkscreen extent -122,-122 119,118
LED_LTST-C171 [mm] "LITE-ON"
  rect 1.2x1.2 smd: 1(-1.05,0) 2(1.05,0)
  silkscreen extent -1.6,-1 2.2,1, body extent -1.05,-0.67 1.05,0.67, height 0.8
LTST-C170TBKT_Blue [mm] "LITE-ON"
  rect 1.2x1.2 smd: 1(-1.05,0) 2(1.05,0)
  silkscreen extent -1.6,-1 2.2,1, body extent -1.05,-0.67 1.05,0.67, height 1.2
Molex_1051640001 [mm] "Receptacle, USB 2.0, Micro B, 5 Pos, 0.65mm Pitch, R/A, SMT"
  rrect22% 0.45x1.38 smd: 1(1.3,4.11) 2(0.65,4.11) 3(0,4.11) 4(-0.65,4.11) 5(-1.3,4.11)
  rrect7% 1.475x2.1 smd: 6(-2.462,3.75) 11(2.462,3.75)
  rrect100% 1.4x2.1 hole 0.6 slot 1.3 at 90 deg: 7(-3.95,1.45) 10(3.95,1.45)
  rrect7% 1.375x1.9 smd: 8(-0.937,1.45) 9(0.937,1.45)
  silkscreen extent 1.2,5.1 1.4,5.4, body extent -4.1,-0.7 4.1,4.47, height 2.45
NDK_NX3225GA [mm] "NDK"
  rect 1.2x1.4 smd: 1(-0.8,1.1) 2(-0.8,-1.1) 3(0.8,-1.1) 4(0.8,1.1)
  silkscreen extent -1.9,-0.1 1.4,2, body extent -1.3,-1.65 1.3,1.65, height 0.9
NPTH125mil [mil]
  round 120 hole 125 unplated mask+15: 1(0,0)
PDT0128A [mm] "Thin QFP, 128-Leads, Body 14x14mm, Pitch 0.4mm"
  oval 1.4x0.2 smd: 1(-7.7,6.2) 2(-7.7,5.8) 3(-7.7,5.4) 4(-7.7,5) 5(-7.7,4.6) 6(-7.7,4.2) 7(-7.7,3.8) 8(-7.7,3.4) 9(-7.7,3) 10(-7.7,2.6) 11(-7.7,2.2) 12(-7.7,1.8) 13(-7.7,1.4) 14(-7.7,1) 15(-7.7,0.6) 16(-7.7,0.2) 17(-7.7,-0.2) 18(-7.7,-0.6) 19(-7.7,-1) 20(-7.7,-1.4) 21(-7.7,-1.8) 22(-7.7,-2.2) 23(-7.7,-2.6) 24(-7.7,-3) 25(-7.7,-3.4) 26(-7.7,-3.8) 27(-7.7,-4.2) 28(-7.7,-4.6) 29(-7.7,-5) 30(-7.7,-5.4) 31(-7.7,-5.8) 32(-7.7,-6.2) 65(7.7,-6.2) 66(7.7,-5.8) 67(7.7,-5.4) 68(7.7,-5) 69(7.7,-4.6) 70(7.7,-4.2) 71(7.7,-3.8) 72(7.7,-3.4) 73(7.7,-3) 74(7.7,-2.6) 75(7.7,-2.2) 76(7.7,-1.8) 77(7.7,-1.4) 78(7.7,-1) 79(7.7,-0.6) 80(7.7,-0.2) 81(7.7,0.2) 82(7.7,0.6) 83(7.7,1) 84(7.7,1.4) 85(7.7,1.8) 86(7.7,2.2) 87(7.7,2.6) 88(7.7,3) 89(7.7,3.4) 90(7.7,3.8) 91(7.7,4.2) 92(7.7,4.6) 93(7.7,5) 94(7.7,5.4) 95(7.7,5.8) 96(7.7,6.2)
  oval 0.2x1.4 smd: 33(-6.2,-7.7) 34(-5.8,-7.7) 35(-5.4,-7.7) 36(-5,-7.7) 37(-4.6,-7.7) 38(-4.2,-7.7) 39(-3.8,-7.7) 40(-3.4,-7.7) 41(-3,-7.7) 42(-2.6,-7.7) 43(-2.2,-7.7) 44(-1.8,-7.7) 45(-1.4,-7.7) 46(-1,-7.7) 47(-0.6,-7.7) 48(-0.2,-7.7) 49(0.2,-7.7) 50(0.6,-7.7) 51(1,-7.7) 52(1.4,-7.7) 53(1.8,-7.7) 54(2.2,-7.7) 55(2.6,-7.7) 56(3,-7.7) 57(3.4,-7.7) 58(3.8,-7.7) 59(4.2,-7.7) 60(4.6,-7.7) 61(5,-7.7) 62(5.4,-7.7) 63(5.8,-7.7) 64(6.2,-7.7) 97(6.2,7.7) 98(5.8,7.7) 99(5.4,7.7) 100(5,7.7) 101(4.6,7.7) 102(4.2,7.7) 103(3.8,7.7) 104(3.4,7.7) 105(3,7.7) 106(2.6,7.7) 107(2.2,7.7) 108(1.8,7.7) 109(1.4,7.7) 110(1,7.7) 111(0.6,7.7) 112(0.2,7.7) 113(-0.2,7.7) 114(-0.6,7.7) 115(-1,7.7) 116(-1.4,7.7) 117(-1.8,7.7) 118(-2.2,7.7) 119(-2.6,7.7) 120(-3,7.7) 121(-3.4,7.7) 122(-3.8,7.7) 123(-4.2,7.7) 124(-4.6,7.7) 125(-5,7.7) 126(-5.4,7.7) 127(-5.8,7.7) 128(-6.2,7.7)
  silkscreen extent -7.7,-6.3 6.3,6.99, body extent -8,-8 8,8, height 1.07
PN0080A-MFG [mm]
  oval 1.45x0.3 smd: 1(-6.725,4.75) 2(-6.725,4.25) 3(-6.725,3.75) 4(-6.725,3.25) 5(-6.725,2.75) 6(-6.725,2.25) 7(-6.725,1.75) 8(-6.725,1.25) 9(-6.725,0.75) 10(-6.725,0.25) 11(-6.725,-0.25) 12(-6.725,-0.75) 13(-6.725,-1.25) 14(-6.725,-1.75) 15(-6.725,-2.25) 16(-6.725,-2.75) 17(-6.725,-3.25) 18(-6.725,-3.75) 19(-6.725,-4.25) 20(-6.725,-4.75) 41(6.725,-4.75) 42(6.725,-4.25) 43(6.725,-3.75) 44(6.725,-3.25) 45(6.725,-2.75) 46(6.725,-2.25) 47(6.725,-1.75) 48(6.725,-1.25) 49(6.725,-0.75) 50(6.725,-0.25) 51(6.725,0.25) 52(6.725,0.75) 53(6.725,1.25) 54(6.725,1.75) 55(6.725,2.25) 56(6.725,2.75) 57(6.725,3.25) 58(6.725,3.75) 59(6.725,4.25) 60(6.725,4.75)
  oval 0.3x1.45 smd: 21(-4.75,-6.725) 22(-4.25,-6.725) 23(-3.75,-6.725) 24(-3.25,-6.725) 25(-2.75,-6.725) 26(-2.25,-6.725) 27(-1.75,-6.725) 28(-1.25,-6.725) 29(-0.75,-6.725) 30(-0.25,-6.725) 31(0.25,-6.725) 32(0.75,-6.725) 33(1.25,-6.725) 34(1.75,-6.725) 35(2.25,-6.725) 36(2.75,-6.725) 37(3.25,-6.725) 38(3.75,-6.725) 39(4.25,-6.725) 40(4.75,-6.725) 61(4.75,6.725) 62(4.25,6.725) 63(3.75,6.725) 64(3.25,6.725) 65(2.75,6.725) 66(2.25,6.725) 67(1.75,6.725) 68(1.25,6.725) 69(0.75,6.725) 70(0.25,6.725) 71(-0.25,6.725) 72(-0.75,6.725) 73(-1.25,6.725) 74(-1.75,6.725) 75(-2.25,6.725) 76(-2.75,6.725) 77(-3.25,6.725) 78(-3.75,6.725) 79(-4.25,6.725) 80(-4.75,6.725)
  silkscreen extent -6.85,-5.6 5.6,5.6, body extent -7.5,-7.5 7.5,7.5, height 0.25
PW0016A-MFG [mm]
  rrect22% 1.5x0.45 smd paste+0 mask+0: 1(-2.9,2.275) 2(-2.9,1.625) 3(-2.9,0.975) 4(-2.9,0.325) 5(-2.9,-0.325) 6(-2.9,-0.975) 7(-2.9,-1.625) 8(-2.9,-2.275) 9(2.9,-2.275) 10(2.9,-1.625) 11(2.9,-0.975) 12(2.9,-0.325) 13(2.9,0.325) 14(2.9,0.975) 15(2.9,1.625) 16(2.9,2.275)
  silkscreen extent -4.38,-2.55 1.78,2.55, body extent -3.75,-2.8 3.75,2.8, height 0.25
PW0024A_N [mm] "TSOP, 24-Leads, Body 7.8x4.4mm, Pitch 0.65mm, IPC Medium Density"
  oval 1.4x0.45 smd: 1(-2.95,3.575) 2(-2.95,2.925) 3(-2.95,2.275) 4(-2.95,1.625) 5(-2.95,0.975) 6(-2.95,0.325) 7(-2.95,-0.325) 8(-2.95,-0.975) 9(-2.95,-1.625) 10(-2.95,-2.275) 11(-2.95,-2.925) 12(-2.95,-3.575) 13(2.95,-3.575) 14(2.95,-2.925) 15(2.95,-2.275) 16(2.95,-1.625) 17(2.95,-0.975) 18(2.95,-0.325) 19(2.95,0.325) 20(2.95,0.975) 21(2.95,1.625) 22(2.95,2.275) 23(2.95,2.925) 24(2.95,3.575)
  silkscreen extent -3.51,-3.95 1.6,4.04, body extent -3.21,-3.9 3.21,3.9, height 1
RSE0008A [mm] "QFN, 8-Leads, Body 1.5x1.5mm, Pitch 0.5mm, TI Recommended"
  rrect40% 0.55x0.25 smd: 1(-0.675,0.5) 3(-0.675,-0.5) 5(0.675,-0.5) 7(0.675,0.5)
  rrect50% 0.55x0.2 smd: 2(-0.675,0) 6(0.675,0)
  rrect33% 0.3x0.6 smd: 4(0,-0.65) 8(0,0.65)
  silkscreen extent -1.02,-0.93 0.78,0.93, body extent -0.75,-0.75 0.75,0.75, height 0.6
Samtec_FTSH-105-01-x-DV-K [mm] "Header(Shrouded), 1.27mm, 5x2, SMT"
  rect 2.79x0.74 smd: 1(-2.035,2.54) 2(2.035,2.54) 3(-2.035,1.27) 4(2.035,1.27) 5(-2.035,0) 6(2.035,0) 7(-2.035,-1.27) 8(2.035,-1.27) 9(-2.035,-2.54) 10(2.035,-2.54)
  silkscreen extent -3.73,-3.48 3.73,3.48, body extent -2.92,-3.18 2.92,3.17, height 6.13
SOD-123 [mm] "On Semi recommended land pattern"
  rect 0.915x1.22 smd: 1(-1.637,0) 2(1.637,0)
  silkscreen extent -2.74,-1.17 2.03,1.17, body extent -1.93,-0.9 1.93,0.9, height 1.35
SOIC-16 [mm] "SOIC, 16-Leads, Body 10.3x7.5mm, Pitch 1.27mm"
  rrect15% 2.25x0.65 smd: 1(-4.75,4.445) 2(-4.75,3.175) 3(-4.75,1.905) 4(-4.75,0.635) 5(-4.75,-0.635) 6(-4.75,-1.905) 7(-4.75,-3.175) 8(-4.75,-4.445) 9(4.75,-4.445) 10(4.75,-3.175) 11(4.75,-1.905) 12(4.75,-0.635) 13(4.75,0.635) 14(4.75,1.905) 15(4.75,3.175) 16(4.75,4.445)
  silkscreen extent -4.87,-5.25 3.8,5.44, body extent -5.32,-5.24 5.32,5.25, height 2.64
SW_1188E [mm] "SMD, 4-Leads, Body 7.8x3.5mm"
  rrect10% 1x1.45 smd: 1(-1.1,3.375) 2(-1.1,-3.375)
  rrect11% 1.3x0.9 smd: 3(0.7,2.1) 4(0.7,-2.1)
  round 0 hole 0.9 unplated mask+0.051: ""(-0.35,1.15) ""(-0.35,-1.15)
  silkscreen extent -1.98,-2.28 0.95,2.28, body extent -2.55,-3.9 1.05,3.9, height 3.5
SW_CAS-220TA [mm] "COPAL ELECTRONICS"
  rect 1.6x1 smd: 1(-1.85,1.75) 2(-1.85,0) 3(-1.85,-1.75) 4(1.85,1.75) 5(1.85,0) 6(1.85,-1.75)
  silkscreen extent -2.1,-2.9 2,3.7, body extent -2.1,-2.85 2.1,2.85, height 2.51
SW_CAS-D20TA [mm] "SMD, 6-Leads, Body 5.4x3.9mm, Pitch 1.75mm"
  rect 1.6x1 smd: 1(-1.85,1.75) 2(-1.85,0) 3(-1.85,-1.75) 4(1.85,1.75) 5(1.85,0) 6(1.85,-1.75)
  silkscreen extent -1.95,-2.7 1.95,2.9, body extent -2.1,-2.7 2.1,2.7, height 2.5
Tag_TC2050-NL [mil] "Footprint for Tag-Connect TC2050 No-Legs cables"
  round 31 smd paste-15.75: 1(-25,100) 2(-25,50) 3(-25,0) 4(-25,-50) 5(-25,-100) 6(25,-100) 7(25,-50) 8(25,0) 9(25,50) 10(25,100)
  round 39 hole 39 unplated: MH1(0,150) MH2(-40,-150) MH3(40,-150)
  silkscreen extent -105,-200 75,200
TI_Stacked_Overlay_Small [mil]
  silkscreen extent -418,-98 418,98
TI_Symbol_Overlay_Small [mil]
  silkscreen extent -90,-88 91,88
TP_50MIL-25MILHOLE [mil]
  round 50 hole 25: 1(0,0)
TSW-102-07-G-D [mm] "Samtec 100mil, 2x2, 230 mil above insulator"
  rrect6% 1.65x1.65 hole 1.016: 1(-1.27,-1.27)
  round 1.65 hole 1.016: 2(-1.27,1.27) 3(1.27,-1.27) 4(1.27,1.27)
  silkscreen extent -3.56,-2.54 2.54,2.54, body extent -2.54,-2.54 2.54,2.54, height 8.38
TSW-104-07-G-D [mm] "Samtec 100mil, 2x4, 230 mil above insulator"
  rrect6% 1.65x1.65 hole 1.016: 1(-3.81,-1.27)
  round 1.65 hole 1.016: 2(-3.81,1.27) 3(-1.27,-1.27) 4(-1.27,1.27) 5(1.27,-1.27) 6(1.27,1.27) 7(3.81,-1.27) 8(3.81,1.27)
  silkscreen extent -6.11,-2.54 5.08,2.54, body extent -5.08,-2.54 5.08,2.54, height 8.38
TSW-105-07-G-D [mm] "Samtec 100mil, 2x5, 230 mil above insulator"
  rrect6% 1.65x1.65 hole 1.016: 1(-5.08,-1.27)
  round 1.65 hole 1.016: 2(-5.08,1.27) 3(-2.54,-1.27) 4(-2.54,1.27) 5(0,-1.27) 6(0,1.27) 7(2.54,-1.27) 8(2.54,1.27) 9(5.08,-1.27) 10(5.08,1.27)
  silkscreen extent -7.37,-2.54 6.35,2.54, body extent -6.35,-2.54 6.35,2.54, height 8.38
TSW-105-07-X-S [mm] "Samtec 100mil, 1x5, 230 mil above insulator"
  rrect6% 1.65x1.65 hole 1.016: 1(-5.08,-0.025)
  round 1.65 hole 1.016: 2(-2.54,0) 3(0,0) 4(2.54,0) 5(5.08,0)
  silkscreen extent -7.05,-1.25 6.37,1.25, body extent -6.35,-1.27 6.35,1.27, height 8.38
WE-TPC_2828 [mm] "WURTH"
  rect 1x3.2 smd: 1(-1.1,0) 2(1.1,0)
  body extent -1.5,-1.5 1.5,1.5, height 3
WEEE_Minimum [mil] "WEEElie bin"
  silkscreen extent -95,-172 99,104
WL-SMCW_RED_0805 [mm] "SMD, 2-Leads, Body 1.6x0.8mm"
  rect 1.1x1.2 smd: 1(-1.05,0) 2(1.05,0)
  silkscreen extent -2.4,-1.1 1.5,1.1, body extent -1,-0.62 1,0.63, height 0.7
Wurth_60900213421 [mil] "Shunt, 2.54mm, Black"
  round 1 on Mech3: 0(0,0)
  body extent -98,-48 98,48, height 338
WURTH_61300211121 [mm] "Header, 2.54mm, 2x1, TH"
  rect 1.65x1.65 hole 1.15: 1(-1.27,0)
  round 1.65 hole 1.15: 2(1.27,0)
  silkscreen extent -2.54,-1.27 2.54,1.6, body extent -2.54,-1.27 2.54,1.27, height 8.54
WURTH_61300311121 [mm] "Header, 2.54mm, 3x1, TH"
  rect 1.65x1.65 hole 1.15: 1(-2.54,0)
  round 1.65 hole 1.15: 2(0,0) 3(2.54,0)
  silkscreen extent -3.81,-1.65 3.81,1.27, body extent -3.81,-1.27 3.81,1.27, height 8.54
